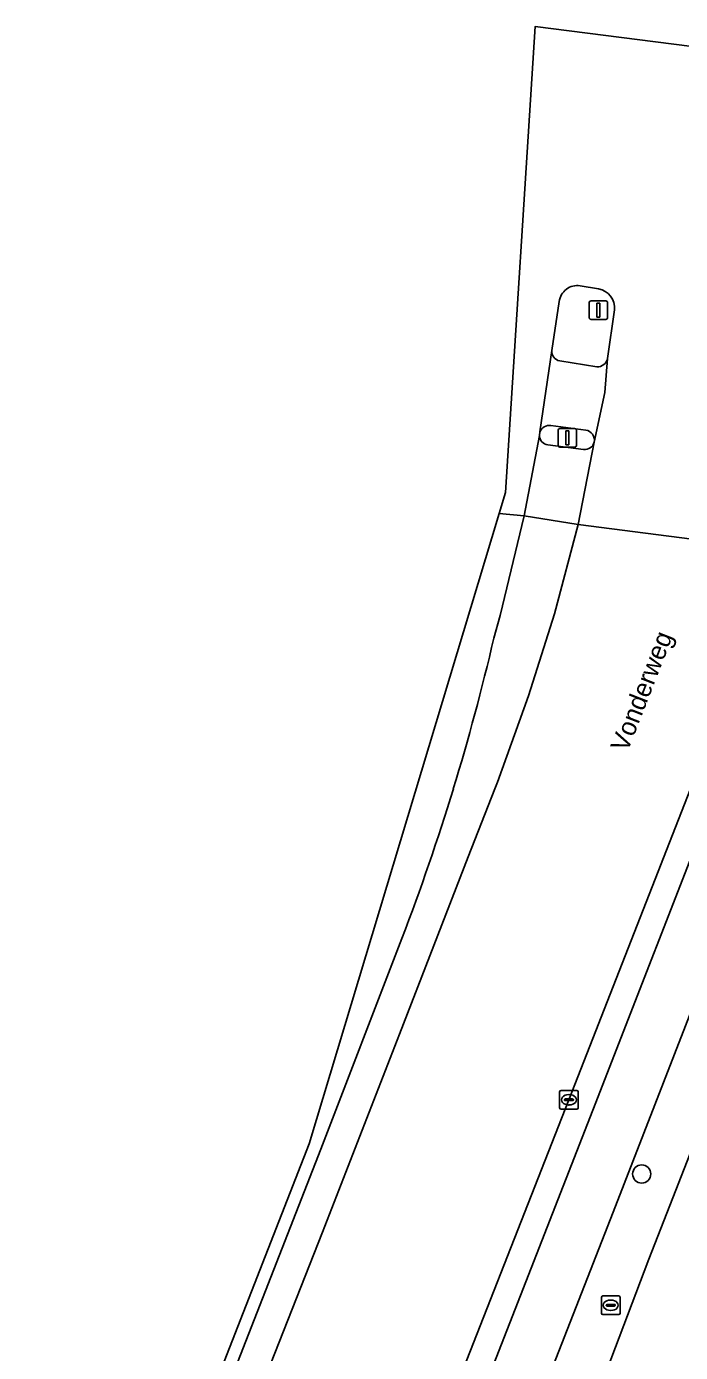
# Model space of a CAD drawing. Extents: x 160663 to 161506, y 382245 to 383291.
# Drawn here: x 160662.6 to 160697.8, y 383219.7 to 383291 of the extents above; entities that cross this region are included whole.
import ezdxf

# ---------------------------------------------------------------- set-up
doc = ezdxf.new("R2010")
doc.units = 0
for name, color, linetype in [('IMGEO_Berm_gesloten', 7, 'Continuous'), ('IMGEO_Berm_open', 7, 'Continuous'), ('IMGEO_Boom', 7, 'Continuous'), ('IMGEO_Brandkraan', 7, 'Continuous'), ('IMGEO_Erf', 7, 'Continuous'), ('IMGEO_Fietspad_gesloten', 7, 'Continuous'), ('IMGEO_Fietspad_open', 7, 'Continuous'), ('IMGEO_Kolk', 7, 'Continuous'), ('IMGEO_Openbare_ruimte_label', 7, 'Continuous'), ('IMGEO_Rijbaan_lokaal_gesloten', 7, 'Continuous'), ('IMGEO_Verkeerseiland_gesloten', 7, 'Continuous'), ('IMGEO_Verkeersregelinstallatiepaal', 7, 'Continuous'), ('IMGEO_Voetpad_open', 7, 'Continuous')]:
    doc.layers.add(name, color=color, linetype=linetype)

msp = doc.modelspace()

# ---------------------------------------------------------------- linework, layer by layer
at = {"layer": 'IMGEO_Berm_gesloten'}
for points in [[(160682.646, 383236.805), (160686.337, 383246.342), (160687.77, 383250), (160687.843, 383250.182), (160687.913, 383250.364), (160689.589, 383254.993), (160690.982, 383259.406), (160692.25, 383264.212), (160689.344, 383264.684), (160688.057, 383259.324), (160687.72, 383258.106)], [(160682.777, 383241.96), (160678.423, 383230.617), (160671.403, 383212.676)], [(160671.509, 383208.353), (160672.921, 383211.969), (160678.504, 383226.154), (160682.646, 383236.805)]]:
    msp.add_lwpolyline(points, dxfattribs=at)
for centre, radius, start, end in [((160562.276, 383287.487), 128.838, 343.08356, 346.81799), ((160562.825, 383287.687), 128.372, 339.13285, 342.92713)]:
    msp.add_arc(centre, radius, start, end, dxfattribs=at)
at = {"layer": 'IMGEO_Berm_open'}
msp.add_lwpolyline([(160676.527, 383187.847), (160678.329, 383194.283), (160680.92, 383201.675), (160693.034, 383232.719), (160699.754, 383250), (160704.215, 383261.301), (160704.704, 383262.55), (160703.286, 383262.794), (160702.787, 383261.521), (160699.61, 383253.4), (160698.283, 383250), (160691.754, 383233.279), (160684.248, 383214.133), (160679.772, 383202.618)], dxfattribs=at)
at = {"layer": 'IMGEO_Boom'}
msp.add_circle((160695.669, 383229.29), 0.489, dxfattribs=at)
at = {"layer": 'IMGEO_Brandkraan'}
for p, q in [((160693.504, 383221.803), (160693.504, 383222.655)), ((160693.579, 383222.729), (160694.431, 383222.729)), ((160693.992, 383222.509), (160694.017, 383222.509)), ((160694.505, 383222.655), (160694.505, 383221.803)), ((160694.431, 383221.729), (160693.579, 383221.729)), ((160693.763, 383222.223), (160693.763, 383222.235)), ((160694.201, 383222.186), (160693.803, 383222.186)), ((160693.806, 383222.272), (160694.204, 383222.272)), ((160694.015, 383221.949), (160693.99, 383221.949)), ((160694.247, 383222.235), (160694.247, 383222.223))]:
    msp.add_line(p, q, dxfattribs=at)
for points in [[(160693.504, 383221.803), (160693.504, 383222.655)], [(160693.579, 383222.729), (160694.431, 383222.729)], [(160694.505, 383222.655), (160694.505, 383221.803)], [(160694.431, 383221.729), (160693.579, 383221.729)]]:
    msp.add_lwpolyline(points, dxfattribs=at)
for centre, radius, start, end in [((160693.581, 383222.653), 0.0765, 91.55205, 178.44795), ((160693.581, 383222.653), 0.0765, 91.55205, 178.44795), ((160694.429, 383222.653), 0.0765, 1.55205, 88.44795), ((160694.429, 383222.653), 0.0765, 1.55205, 88.44795), ((160693.581, 383221.805), 0.0765, 181.55205, 268.44795), ((160693.581, 383221.805), 0.0765, 181.55205, 268.44795), ((160693.803, 383222.232), 0.0403, 85.87752, 175.75265), ((160693.8, 383222.222), 0.0366, 178.93798, 274.71019), ((160694.204, 383222.229), 0.043, 264.86636, 352.45326), ((160694.208, 383222.234), 0.0386, 1.73085, 96.63898), ((160694.429, 383221.805), 0.0765, 271.55205, 358.44795), ((160694.429, 383221.805), 0.0765, 271.55205, 358.44795)]:
    msp.add_arc(centre, radius, start, end, dxfattribs=at)
for centre, major_axis, ratio, start_param, end_param in [((160693.991, 383222.229), (-0.387, 0.002), 0.722429, 4.712389, 7.853982), ((160694.016, 383222.229), (-0.39, 0.002), 0.717154, 1.570796, 4.712389)]:
    msp.add_ellipse(centre, major_axis=major_axis, ratio=ratio, start_param=start_param, end_param=end_param, dxfattribs=at)
at = {"layer": 'IMGEO_Erf'}
msp.add_lwpolyline([(160711.688, 383264.077), (160710.823, 383262.636), (160705.938, 383250), (160696.054, 383224.71), (160694.007, 383219.314)], dxfattribs=at)
at = {"layer": 'IMGEO_Fietspad_gesloten'}
for points in [[(160690.83, 383273.576), (160690.198, 383269.194)], [(160693.253, 383272.691), (160691.262, 383273.015)], [(160693.116, 383268.643), (160693.693, 383271.306), (160693.834, 383273.143)], [(160690.778, 383269.531), (160692.66, 383269.289)]]:
    msp.add_lwpolyline(points, dxfattribs=at)
for centre, radius, start, end in [((160691.349, 383273.529), 0.521, 174.80749, 260.3889), ((160693.275, 383273.262), 0.571, 267.78301, 347.98061), ((160690.689, 383269.016), 0.522, 80.22132, 160.09481), ((160692.58, 383268.749), 0.546, 348.86576, 81.56943)]:
    msp.add_arc(centre, radius, start, end, dxfattribs=at)
at = {"layer": 'IMGEO_Fietspad_open'}
for points in [[(160709.046, 383265.279), (160709.286, 383265.775), (160706.248, 383266.496), (160704.704, 383262.55), (160704.215, 383261.301), (160699.754, 383250), (160693.034, 383232.719), (160680.92, 383201.675), (160678.329, 383194.283), (160676.527, 383187.847)], [(160680.242, 383190.168), (160681.295, 383193.552), (160682.218, 383196.394), (160682.535, 383197.355), (160683.214, 383199.23), (160684.277, 383202.023), (160694.135, 383227.242), (160702.977, 383250)]]:
    msp.add_lwpolyline(points, dxfattribs=at)
at = {"layer": 'IMGEO_Kolk'}
for p, q in [((160691.329, 383233.779), (160692.181, 383233.779)), ((160691.254, 383232.853), (160691.254, 383233.705)), ((160691.513, 383233.273), (160691.513, 383233.285)), ((160691.951, 383233.236), (160691.553, 383233.236)), ((160691.556, 383233.322), (160691.954, 383233.322)), ((160691.742, 383233.559), (160691.767, 383233.559)), ((160691.997, 383233.285), (160691.997, 383233.273)), ((160692.255, 383233.705), (160692.255, 383232.853)), ((160692.181, 383232.779), (160691.329, 383232.779)), ((160691.765, 383232.999), (160691.74, 383232.999))]:
    msp.add_line(p, q, dxfattribs=at)
for points in [[(160691.329, 383233.779), (160692.181, 383233.779)], [(160691.254, 383232.853), (160691.254, 383233.705)], [(160692.255, 383233.705), (160692.255, 383232.853)], [(160692.181, 383232.779), (160691.329, 383232.779)]]:
    msp.add_lwpolyline(points, dxfattribs=at)
for centre, radius, start, end in [((160691.331, 383233.703), 0.0765, 91.55205, 178.44795), ((160691.331, 383233.703), 0.0765, 91.55205, 178.44795), ((160692.179, 383233.703), 0.0765, 1.55205, 88.44795), ((160692.179, 383233.703), 0.0765, 1.55205, 88.44795), ((160691.553, 383233.282), 0.0403, 85.87752, 175.75265), ((160691.55, 383233.272), 0.0366, 178.93798, 274.71019), ((160691.954, 383233.279), 0.043, 264.86636, 352.45326), ((160691.958, 383233.284), 0.0386, 1.73085, 96.63898), ((160691.331, 383232.855), 0.0765, 181.55205, 268.44795), ((160691.331, 383232.855), 0.0765, 181.55205, 268.44795), ((160692.179, 383232.855), 0.0765, 271.55205, 358.44795), ((160692.179, 383232.855), 0.0765, 271.55205, 358.44795)]:
    msp.add_arc(centre, radius, start, end, dxfattribs=at)
for centre, major_axis, ratio, start_param, end_param in [((160691.741, 383233.279), (-0.387, 0.002), 0.722429, 4.712389, 7.853982), ((160691.766, 383233.279), (-0.39, 0.002), 0.717154, 1.570796, 4.712389)]:
    msp.add_ellipse(centre, major_axis=major_axis, ratio=ratio, start_param=start_param, end_param=end_param, dxfattribs=at)
at = {"layer": 'IMGEO_Rijbaan_lokaal_gesloten'}
for points in [[(160707.258, 383287.689), (160711.312, 383287.33), (160711.318, 383288.264), (160689.936, 383290.992), (160688.345, 383265.938), (160688.005, 383264.811)], [(160692.358, 383277.054), (160693.34, 383276.895)], [(160688.005, 383264.811), (160689.344, 383264.684), (160690.168, 383269.002), (160690.198, 383269.194), (160690.83, 383273.576), (160691.236, 383276.206)], [(160694.198, 383275.753), (160693.834, 383273.143), (160693.693, 383271.306), (160693.116, 383268.643), (160692.25, 383264.212), (160695.864, 383263.748), (160699.635, 383263.263), (160703.286, 383262.794), (160704.804, 383266.667), (160705.165, 383267.603), (160707.201, 383272.874), (160708.359, 383274.57)], [(160687.72, 383258.106), (160688.057, 383259.324), (160689.344, 383264.684), (160688.005, 383264.811), (160677.782, 383230.912), (160664.085, 383195.806), (160662.59, 383174.443), (160662.741, 383172.971), (160664.567, 383155.247), (160669.029, 383139.828), (160669.397, 383138.878), (160670.641, 383135.865), (160671.51, 383134.28)], [(160691.754, 383233.279), (160698.283, 383250), (160699.61, 383253.4), (160702.787, 383261.521), (160703.286, 383262.794), (160699.635, 383263.263), (160695.864, 383263.748), (160692.25, 383264.212), (160690.982, 383259.406), (160689.589, 383254.993), (160687.913, 383250.364), (160687.843, 383250.182), (160687.77, 383250), (160686.337, 383246.342), (160682.646, 383236.805), (160678.504, 383226.154), (160672.921, 383211.969), (160671.509, 383208.353)], [(160671.403, 383212.676), (160678.423, 383230.617), (160682.777, 383241.96)], [(160679.772, 383202.618), (160684.248, 383214.133), (160691.754, 383233.279)]]:
    msp.add_lwpolyline(points, dxfattribs=at)
for centre, radius, start, end in [((160692.212, 383276.081), 0.984, 81.48162, 172.68187), ((160693.15, 383275.859), 1.053, 354.21425, 79.62182), ((160562.276, 383287.487), 128.838, 343.08356, 346.81799), ((160562.825, 383287.687), 128.372, 339.13285, 342.92713)]:
    msp.add_arc(centre, radius, start, end, dxfattribs=at)
at = {"layer": 'IMGEO_Verkeerseiland_gesloten'}
for points in [[(160693.34, 383276.895), (160692.358, 383277.054)], [(160691.236, 383276.206), (160690.83, 383273.576)], [(160693.834, 383273.143), (160694.198, 383275.753)], [(160691.262, 383273.015), (160693.253, 383272.691)], [(160692.66, 383269.289), (160690.778, 383269.531)], [(160690.198, 383269.194), (160690.168, 383269.002)], [(160690.628, 383268.5), (160692.544, 383268.25)]]:
    msp.add_lwpolyline(points, dxfattribs=at)
for centre, radius, start, end in [((160692.212, 383276.081), 0.984, 81.48162, 172.68187), ((160693.15, 383275.859), 1.053, 354.21425, 79.62182), ((160691.349, 383273.529), 0.521, 174.80749, 260.3889), ((160693.275, 383273.262), 0.571, 267.78301, 347.98061), ((160690.689, 383269.016), 0.522, 80.22132, 160.09481), ((160690.689, 383269.017), 0.521, 181.68281, 263.3174), ((160692.58, 383268.749), 0.546, 348.86576, 81.56943), ((160692.609, 383268.768), 0.522, 262.86678, 346.11625)]:
    msp.add_arc(centre, radius, start, end, dxfattribs=at)
at = {"layer": 'IMGEO_Verkeersregelinstallatiepaal'}
for p, q in [((160692.843, 383275.34), (160692.843, 383276.14)), ((160692.843, 383276.14), (160692.843, 383275.34)), ((160692.943, 383276.24), (160693.733, 383276.24)), ((160693.733, 383276.24), (160692.943, 383276.24)), ((160693.833, 383276.14), (160693.833, 383275.34)), ((160693.833, 383275.34), (160693.833, 383276.14)), ((160693.733, 383275.24), (160692.943, 383275.24)), ((160692.943, 383275.24), (160693.733, 383275.24)), ((160691.171, 383268.474), (160691.171, 383269.274)), ((160691.171, 383269.274), (160691.171, 383268.474)), ((160691.271, 383269.374), (160692.061, 383269.374)), ((160692.061, 383269.374), (160691.271, 383269.374)), ((160692.161, 383269.274), (160692.161, 383268.474)), ((160692.161, 383268.474), (160692.161, 383269.274)), ((160692.061, 383268.374), (160691.271, 383268.374)), ((160691.271, 383268.374), (160692.061, 383268.374))]:
    msp.add_line(p, q, dxfattribs=at)
for points in [[(160693.263, 383276.115), (160693.413, 383276.115), (160693.413, 383275.365), (160693.263, 383275.365), (160693.263, 383276.115)], [(160691.591, 383269.249), (160691.741, 383269.249), (160691.741, 383268.499), (160691.591, 383268.499), (160691.591, 383269.249)]]:
    msp.add_lwpolyline(points, dxfattribs=at)
for centre, start, end in [((160692.943, 383276.14), 90, 180), ((160692.943, 383276.14), 90, 180), ((160693.733, 383276.14), 0, 90), ((160693.733, 383276.14), 360, 90), ((160692.943, 383275.34), 180, 270), ((160692.943, 383275.34), 180, 270), ((160693.733, 383275.34), 270, 0), ((160693.733, 383275.34), 270, 0), ((160691.271, 383269.274), 90, 180), ((160691.271, 383269.274), 90, 180), ((160692.061, 383269.274), 0, 90), ((160692.061, 383269.274), 360, 90), ((160691.271, 383268.474), 180, 270), ((160691.271, 383268.474), 180, 270), ((160692.061, 383268.474), 270, 0), ((160692.061, 383268.474), 270, 0)]:
    msp.add_arc(centre, 0.1, start, end, dxfattribs=at)
at = {"layer": 'IMGEO_Voetpad_open'}
for points in [[(160690.168, 383269.002), (160689.344, 383264.684), (160692.25, 383264.212), (160693.116, 383268.643)], [(160692.544, 383268.25), (160690.628, 383268.5)], [(160686.447, 383200.495), (160687.258, 383202.55), (160687.445, 383202.529), (160694.007, 383219.314), (160696.054, 383224.71), (160705.938, 383250), (160710.823, 383262.636), (160711.688, 383264.077), (160709.046, 383265.279)], [(160708.654, 383264.342), (160707.163, 383260.667), (160702.977, 383250), (160694.135, 383227.242), (160684.277, 383202.023), (160683.214, 383199.23), (160682.535, 383197.355), (160682.218, 383196.394), (160681.295, 383193.552), (160680.242, 383190.168)]]:
    msp.add_lwpolyline(points, dxfattribs=at)
for centre, radius, start, end in [((160690.689, 383269.017), 0.521, 181.68281, 263.3174), ((160692.609, 383268.768), 0.522, 262.86678, 346.11625)]:
    msp.add_arc(centre, radius, start, end, dxfattribs=at)

# ---------------------------------------------------------------- texts
at = {"layer": 'IMGEO_Openbare_ruimte_label'}
msp.add_text('Vonderweg', height=1, rotation=68.66647, dxfattribs=at).set_placement((160694.894, 383251.922))

doc.saveas('drawing.dxf')
